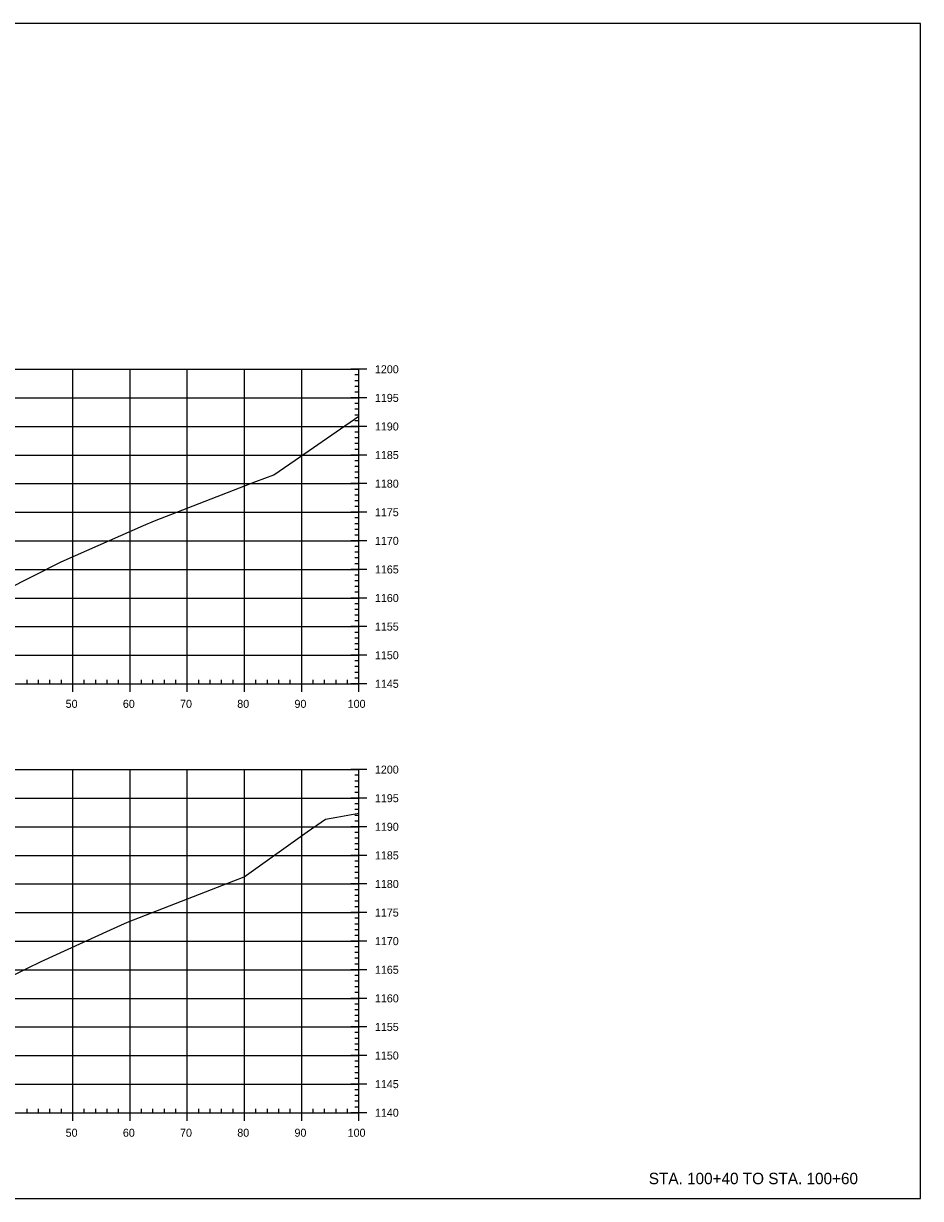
# Model space of a CAD drawing. Extents: x 688474 to 694748, y 765018 to 767373.
# Drawn here: x 689779.2 to 689936, y 765303.6 to 765509.1 of the extents above; entities that cross this region are included whole.
import ezdxf

# ---------------------------------------------------------------- set-up
doc = ezdxf.new("R2010")
doc.units = 0
for name, color, linetype in [('60', 7, 'Continuous'), ('R_Exist Surface', 7, 'Continuous'), ('R_Grid', 7, 'Continuous'), ('R_No Plot', 7, 'Continuous')]:
    doc.layers.add(name, color=color, linetype=linetype)

msp = doc.modelspace()

# ---------------------------------------------------------------- linework, layer by layer
at = {"layer": '60'}
for p, q in [((689839.22, 765448.6), (689836.42, 765448.6)), ((689837.82, 765447.6), (689837.12, 765447.6)), ((689837.82, 765393.6), (689837.82, 765448.6)), ((689837.82, 765446.6), (689837.12, 765446.6)), ((689837.82, 765445.6), (689837.12, 765445.6)), ((689839.22, 765443.6), (689836.42, 765443.6)), ((689837.82, 765444.6), (689837.12, 765444.6)), ((689837.82, 765442.6), (689837.12, 765442.6)), ((689837.82, 765441.6), (689837.12, 765441.6)), ((689837.82, 765440.6), (689837.12, 765440.6)), ((689837.82, 765439.6), (689837.12, 765439.6)), ((689839.22, 765438.6), (689836.42, 765438.6)), ((689837.82, 765437.6), (689837.12, 765437.6)), ((689837.82, 765436.6), (689837.12, 765436.6)), ((689837.82, 765435.6), (689837.12, 765435.6)), ((689839.22, 765433.6), (689836.42, 765433.6)), ((689837.82, 765434.6), (689837.12, 765434.6)), ((689837.82, 765432.6), (689837.12, 765432.6)), ((689837.82, 765431.6), (689837.12, 765431.6)), ((689837.82, 765430.6), (689837.12, 765430.6)), ((689837.82, 765429.6), (689837.12, 765429.6)), ((689839.22, 765428.6), (689836.42, 765428.6)), ((689837.82, 765427.6), (689837.12, 765427.6)), ((689837.82, 765426.6), (689837.12, 765426.6)), ((689837.82, 765425.6), (689837.12, 765425.6)), ((689839.22, 765423.6), (689836.42, 765423.6)), ((689837.82, 765424.6), (689837.12, 765424.6)), ((689837.82, 765422.6), (689837.12, 765422.6)), ((689837.82, 765421.6), (689837.12, 765421.6)), ((689837.82, 765420.6), (689837.12, 765420.6)), ((689837.82, 765419.6), (689837.12, 765419.6)), ((689839.22, 765418.6), (689836.42, 765418.6)), ((689837.82, 765417.6), (689837.12, 765417.6)), ((689837.82, 765416.6), (689837.12, 765416.6)), ((689837.82, 765415.6), (689837.12, 765415.6)), ((689837.82, 765414.6), (689837.12, 765414.6)), ((689839.22, 765413.6), (689836.42, 765413.6)), ((689837.82, 765412.6), (689837.12, 765412.6)), ((689837.82, 765411.6), (689837.12, 765411.6)), ((689837.82, 765410.6), (689837.12, 765410.6)), ((689839.22, 765408.6), (689836.42, 765408.6)), ((689837.82, 765409.6), (689837.12, 765409.6)), ((689837.82, 765407.6), (689837.12, 765407.6)), ((689837.82, 765406.6), (689837.12, 765406.6)), ((689837.82, 765405.6), (689837.12, 765405.6)), ((689837.82, 765404.6), (689837.12, 765404.6)), ((689839.22, 765403.6), (689836.42, 765403.6)), ((689837.82, 765402.6), (689837.12, 765402.6)), ((689837.82, 765401.6), (689837.12, 765401.6)), ((689837.82, 765400.6), (689837.12, 765400.6)), ((689839.22, 765398.6), (689836.42, 765398.6)), ((689837.82, 765399.6), (689837.12, 765399.6)), ((689837.82, 765397.6), (689837.12, 765397.6)), ((689837.82, 765396.6), (689837.12, 765396.6)), ((689779.82, 765393.6), (689779.82, 765394.3)), ((689781.82, 765393.6), (689781.82, 765394.3)), ((689783.82, 765393.6), (689783.82, 765394.3)), ((689785.82, 765393.6), (689785.82, 765394.3)), ((689787.82, 765392.2), (689787.82, 765395)), ((689789.82, 765393.6), (689789.82, 765394.3)), ((689791.82, 765393.6), (689791.82, 765394.3)), ((689793.82, 765393.6), (689793.82, 765394.3)), ((689795.82, 765393.6), (689795.82, 765394.3)), ((689797.82, 765392.2), (689797.82, 765395)), ((689799.82, 765393.6), (689799.82, 765394.3)), ((689801.82, 765393.6), (689801.82, 765394.3)), ((689803.82, 765393.6), (689803.82, 765394.3)), ((689805.82, 765393.6), (689805.82, 765394.3)), ((689807.82, 765392.2), (689807.82, 765395)), ((689809.82, 765393.6), (689809.82, 765394.3)), ((689811.82, 765393.6), (689811.82, 765394.3)), ((689813.82, 765393.6), (689813.82, 765394.3)), ((689815.82, 765393.6), (689815.82, 765394.3)), ((689817.82, 765392.2), (689817.82, 765395)), ((689819.82, 765393.6), (689819.82, 765394.3)), ((689821.82, 765393.6), (689821.82, 765394.3)), ((689823.82, 765393.6), (689823.82, 765394.3)), ((689825.82, 765393.6), (689825.82, 765394.3)), ((689827.82, 765392.2), (689827.82, 765395)), ((689829.82, 765393.6), (689829.82, 765394.3)), ((689831.82, 765393.6), (689831.82, 765394.3)), ((689833.82, 765393.6), (689833.82, 765394.3)), ((689835.82, 765393.6), (689835.82, 765394.3)), ((689837.82, 765395.6), (689837.12, 765395.6)), ((689837.82, 765394.6), (689837.12, 765394.6)), ((689837.82, 765392.2), (689837.82, 765395)), ((689637.82, 765393.6), (689837.82, 765393.6)), ((689839.22, 765393.6), (689836.42, 765393.6)), ((689839.22, 765378.6), (689836.42, 765378.6)), ((689837.82, 765377.6), (689837.12, 765377.6)), ((689837.82, 765318.6), (689837.82, 765378.6)), ((689837.82, 765376.6), (689837.12, 765376.6)), ((689837.82, 765375.6), (689837.12, 765375.6)), ((689839.22, 765373.6), (689836.42, 765373.6)), ((689837.82, 765374.6), (689837.12, 765374.6)), ((689837.82, 765372.6), (689837.12, 765372.6)), ((689837.82, 765371.6), (689837.12, 765371.6)), ((689837.82, 765370.6), (689837.12, 765370.6)), ((689837.82, 765369.6), (689837.12, 765369.6)), ((689839.22, 765368.6), (689836.42, 765368.6)), ((689837.82, 765367.6), (689837.12, 765367.6)), ((689837.82, 765366.6), (689837.12, 765366.6)), ((689837.82, 765365.6), (689837.12, 765365.6)), ((689839.22, 765363.6), (689836.42, 765363.6)), ((689837.82, 765364.6), (689837.12, 765364.6)), ((689837.82, 765362.6), (689837.12, 765362.6)), ((689837.82, 765361.6), (689837.12, 765361.6)), ((689837.82, 765360.6), (689837.12, 765360.6)), ((689837.82, 765359.6), (689837.12, 765359.6)), ((689839.22, 765358.6), (689836.42, 765358.6)), ((689837.82, 765357.6), (689837.12, 765357.6)), ((689837.82, 765356.6), (689837.12, 765356.6)), ((689837.82, 765355.6), (689837.12, 765355.6)), ((689839.22, 765353.6), (689836.42, 765353.6)), ((689837.82, 765354.6), (689837.12, 765354.6)), ((689837.82, 765352.6), (689837.12, 765352.6)), ((689837.82, 765351.6), (689837.12, 765351.6)), ((689837.82, 765350.6), (689837.12, 765350.6)), ((689837.82, 765349.6), (689837.12, 765349.6)), ((689839.22, 765348.6), (689836.42, 765348.6)), ((689837.82, 765347.6), (689837.12, 765347.6)), ((689837.82, 765346.6), (689837.12, 765346.6)), ((689837.82, 765345.6), (689837.12, 765345.6)), ((689839.22, 765343.6), (689836.42, 765343.6)), ((689837.82, 765344.6), (689837.12, 765344.6)), ((689837.82, 765342.6), (689837.12, 765342.6)), ((689837.82, 765341.6), (689837.12, 765341.6)), ((689837.82, 765340.6), (689837.12, 765340.6)), ((689839.22, 765338.6), (689836.42, 765338.6)), ((689837.82, 765339.6), (689837.12, 765339.6)), ((689837.82, 765337.6), (689837.12, 765337.6)), ((689837.82, 765336.6), (689837.12, 765336.6)), ((689837.82, 765335.6), (689837.12, 765335.6)), ((689837.82, 765334.6), (689837.12, 765334.6)), ((689839.22, 765333.6), (689836.42, 765333.6)), ((689837.82, 765332.6), (689837.12, 765332.6)), ((689837.82, 765331.6), (689837.12, 765331.6)), ((689837.82, 765330.6), (689837.12, 765330.6)), ((689839.22, 765328.6), (689836.42, 765328.6)), ((689837.82, 765329.6), (689837.12, 765329.6)), ((689837.82, 765327.6), (689837.12, 765327.6)), ((689837.82, 765326.6), (689837.12, 765326.6)), ((689837.82, 765325.6), (689837.12, 765325.6)), ((689837.82, 765324.6), (689837.12, 765324.6)), ((689839.22, 765323.6), (689836.42, 765323.6)), ((689837.82, 765322.6), (689837.12, 765322.6)), ((689837.82, 765321.6), (689837.12, 765321.6)), ((689837.82, 765320.6), (689837.12, 765320.6)), ((689637.82, 765318.6), (689837.82, 765318.6)), ((689779.82, 765318.6), (689779.82, 765319.3)), ((689781.82, 765318.6), (689781.82, 765319.3)), ((689783.82, 765318.6), (689783.82, 765319.3)), ((689785.82, 765318.6), (689785.82, 765319.3)), ((689787.82, 765317.2), (689787.82, 765320)), ((689789.82, 765318.6), (689789.82, 765319.3)), ((689791.82, 765318.6), (689791.82, 765319.3)), ((689793.82, 765318.6), (689793.82, 765319.3)), ((689795.82, 765318.6), (689795.82, 765319.3)), ((689797.82, 765317.2), (689797.82, 765320)), ((689799.82, 765318.6), (689799.82, 765319.3)), ((689801.82, 765318.6), (689801.82, 765319.3)), ((689803.82, 765318.6), (689803.82, 765319.3)), ((689805.82, 765318.6), (689805.82, 765319.3)), ((689807.82, 765317.2), (689807.82, 765320)), ((689809.82, 765318.6), (689809.82, 765319.3)), ((689811.82, 765318.6), (689811.82, 765319.3)), ((689813.82, 765318.6), (689813.82, 765319.3)), ((689815.82, 765318.6), (689815.82, 765319.3)), ((689817.82, 765317.2), (689817.82, 765320)), ((689819.82, 765318.6), (689819.82, 765319.3)), ((689821.82, 765318.6), (689821.82, 765319.3)), ((689823.82, 765318.6), (689823.82, 765319.3)), ((689825.82, 765318.6), (689825.82, 765319.3)), ((689827.82, 765317.2), (689827.82, 765320)), ((689829.82, 765318.6), (689829.82, 765319.3)), ((689831.82, 765318.6), (689831.82, 765319.3)), ((689833.82, 765318.6), (689833.82, 765319.3)), ((689835.82, 765318.6), (689835.82, 765319.3)), ((689839.22, 765318.6), (689836.42, 765318.6)), ((689837.82, 765319.6), (689837.12, 765319.6)), ((689837.82, 765317.2), (689837.82, 765320))]:
    msp.add_line(p, q, dxfattribs=at)
at = {"layer": 'R_Exist Surface'}
for points in [[(689771.23, 765407.6), (689785.66, 765414.85), (689786.32, 765415.19), (689800.17, 765421.3), (689802.11, 765422.12), (689819.81, 765428.96), (689822.96, 765430.16), (689826.68, 765432.7), (689837.82, 765440.42)], [(689768.73, 765338.31), (689779.88, 765343.87), (689782.26, 765345.07), (689794.39, 765350.6), (689797.36, 765351.9), (689814.15, 765358.46), (689817.79, 765359.87), (689828.8, 765367.7), (689832.01, 765369.93), (689833.96, 765370.3), (689837.82, 765370.98)]]:
    msp.add_lwpolyline(points, dxfattribs=at)
at = {"layer": 'R_Grid'}
for p, q in [((689637.82, 765448.6), (689837.82, 765448.6)), ((689787.82, 765393.6), (689787.82, 765448.6)), ((689797.82, 765393.6), (689797.82, 765448.6)), ((689807.82, 765393.6), (689807.82, 765448.6)), ((689817.82, 765393.6), (689817.82, 765448.6)), ((689827.82, 765393.6), (689827.82, 765448.6)), ((689837.82, 765393.6), (689837.82, 765448.6)), ((689637.82, 765443.6), (689837.82, 765443.6)), ((689637.82, 765438.6), (689837.82, 765438.6)), ((689637.82, 765433.6), (689837.82, 765433.6)), ((689637.82, 765428.6), (689837.82, 765428.6)), ((689637.82, 765423.6), (689837.82, 765423.6)), ((689637.82, 765418.6), (689837.82, 765418.6)), ((689637.82, 765413.6), (689837.82, 765413.6)), ((689637.82, 765408.6), (689837.82, 765408.6)), ((689637.82, 765403.6), (689837.82, 765403.6)), ((689637.82, 765398.6), (689837.82, 765398.6)), ((689637.82, 765393.6), (689837.82, 765393.6)), ((689637.82, 765378.6), (689837.82, 765378.6)), ((689787.82, 765318.6), (689787.82, 765378.6)), ((689797.82, 765318.6), (689797.82, 765378.6)), ((689807.82, 765318.6), (689807.82, 765378.6)), ((689817.82, 765318.6), (689817.82, 765378.6)), ((689827.82, 765318.6), (689827.82, 765378.6)), ((689837.82, 765318.6), (689837.82, 765378.6)), ((689637.82, 765373.6), (689837.82, 765373.6)), ((689637.82, 765368.6), (689837.82, 765368.6)), ((689637.82, 765363.6), (689837.82, 765363.6)), ((689637.82, 765358.6), (689837.82, 765358.6)), ((689637.82, 765353.6), (689837.82, 765353.6)), ((689637.82, 765348.6), (689837.82, 765348.6)), ((689637.82, 765343.6), (689837.82, 765343.6)), ((689637.82, 765338.6), (689837.82, 765338.6)), ((689637.82, 765333.6), (689837.82, 765333.6)), ((689637.82, 765328.6), (689837.82, 765328.6)), ((689637.82, 765323.6), (689837.82, 765323.6)), ((689637.82, 765318.6), (689837.82, 765318.6))]:
    msp.add_line(p, q, dxfattribs=at)
at = {"layer": 'R_No Plot'}
msp.add_lwpolyline([(689619.82, 765303.6), (689936, 765303.6), (689936, 765509.06), (689619.82, 765509.06)], close=True, dxfattribs=at)

# ---------------------------------------------------------------- texts
at = {"layer": '60'}
for s, height, p in [('1200', 1.4, (689840.62, 765447.9)), ('1195', 1.4, (689840.62, 765442.9)), ('1190', 1.4, (689840.62, 765437.9)), ('1185', 1.4, (689840.62, 765432.9)), ('1180', 1.4, (689840.62, 765427.9)), ('1175', 1.4, (689840.62, 765422.9)), ('1170', 1.4, (689840.62, 765417.9)), ('1165', 1.4, (689840.62, 765412.9)), ('1160', 1.4, (689840.62, 765407.9)), ('1155', 1.4, (689840.62, 765402.9)), ('1150', 1.4, (689840.62, 765397.9)), ('1145', 1.4, (689840.62, 765392.9)), ('50', 1.4, (689786.56, 765389.4)), ('60', 1.4, (689796.56, 765389.4)), ('70', 1.4, (689806.56, 765389.4)), ('80', 1.4, (689816.56, 765389.4)), ('90', 1.4, (689826.56, 765389.4)), ('100', 1.4, (689835.86, 765389.4)), ('1200', 1.4, (689840.62, 765377.9)), ('1195', 1.4, (689840.62, 765372.9)), ('1190', 1.4, (689840.62, 765367.9)), ('1185', 1.4, (689840.62, 765362.9)), ('1180', 1.4, (689840.62, 765357.9)), ('1175', 1.4, (689840.62, 765352.9)), ('1170', 1.4, (689840.62, 765347.9)), ('1165', 1.4, (689840.62, 765342.9)), ('1160', 1.4, (689840.62, 765337.9)), ('1155', 1.4, (689840.62, 765332.9)), ('1150', 1.4, (689840.62, 765327.9)), ('1145', 1.4, (689840.62, 765322.9)), ('1140', 1.4, (689840.62, 765317.9)), ('50', 1.4, (689786.56, 765314.4)), ('60', 1.4, (689796.56, 765314.4)), ('70', 1.4, (689806.56, 765314.4)), ('80', 1.4, (689816.56, 765314.4)), ('90', 1.4, (689826.56, 765314.4)), ('100', 1.4, (689835.86, 765314.4)), ('STA. 100+40 TO STA. 100+60', 2, (689888.5, 765306.1))]:
    msp.add_text(s, height=height, dxfattribs=at).set_placement(p)

doc.saveas('drawing.dxf')
